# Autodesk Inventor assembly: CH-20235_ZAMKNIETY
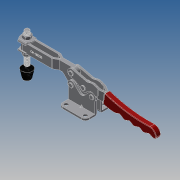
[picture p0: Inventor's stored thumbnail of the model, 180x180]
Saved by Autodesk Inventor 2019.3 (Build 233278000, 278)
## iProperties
Company: ·L?¤¤?
Created: 2010-06
Part Number: CH-20235_ZAMKNIETY
Material: Ogólny
Description: STEP AP203
Document SubType Name: Assembly
Designer: CADENGINEERING4
Sending System: SolidWorks 2005179
Preprocessor: SwSTEP 2.0
Title: CH-20235.STEP
Author: ·L?¥Î?
Revision Number: ANY
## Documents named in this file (9)
- E:\STRONA\Horizontal toggle clamp\CH-20235\CH-20235_ZAMKNIETY.iam
- E:\STRONA\Horizontal toggle clamp\CH-20235\20235-01___.ipt
- E:\STRONA\Horizontal toggle clamp\CH-20235\20235-05___.ipt
- E:\STRONA\Horizontal toggle clamp\CH-20235\20235-02___.ipt
- E:\STRONA\Horizontal toggle clamp\CH-20235\20235-04___.ipt
- E:\STRONA\Horizontal toggle clamp\CH-20235\FW380___.ipt
- E:\STRONA\Horizontal toggle clamp\CH-20235\38312-02___.ipt
- E:\STRONA\Horizontal toggle clamp\CH-20235\CH-FC-38312___.ipt
- E:\STRONA\Horizontal toggle clamp\CH-20235\20235-03___.ipt
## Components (14 placed, 14 different names)
1. 20235-01_??_1 — Zestawiające:13, Zestawiające:14, Zestawiające:15, Zestawiające:16, Zestawiające:21, Zestawiające:22, Zestawiające:23, Zestawiające:24, Przejściowe:1
2. 20235-05_??_2 — Zestawiające:15, Zestawiające:16
3. 20235-05_??_3 — Zestawiające:19, Zestawiające:20
4. 20235-02_??_4 — Zestawiające:7, Zestawiające:8, Kątowe:1, Zestawiające:9, Zestawiające:21, Zestawiające:22, Zestawiające:27
5. 20235-04_??_5 — Zestawiające:10, Zestawiające:11, Zestawiające:12, Zestawiające:13, Zestawiające:14, Zestawiające:17, Zestawiające:18
6. FW380_??_6 — Zestawiające:4, Zestawiające:6, Zestawiające:8, Równoległe:2, Kątowe:1
7. 38312-02_??_7 — Zestawiające:1, Zestawiające:3
8. 20235-05_??_8 — Zestawiające:23, Zestawiające:24
9. 20235-04_??_9 — Zestawiające:10, Zestawiające:11, Zestawiające:12
10. 38312-02_??_10 — Zestawiające:5, Zestawiające:6, Równoległe:1
11. CH-FC-38312_??_11 — Zestawiające:1, Zestawiające:2, Zestawiające:4, Zestawiające:5, Równoległe:1, Zestawiające:9
12. 20235-05_??_12 — Zestawiające:25, Zestawiające:26, Zestawiające:27
13. FW380_??_13 — Zestawiające:2, Zestawiające:3, Zestawiające:7, Równoległe:2
14. 20235-03_??_14 — Zestawiające:17, Zestawiające:18, Zestawiające:19, Zestawiające:20, Zestawiające:25, Zestawiające:26, Przejściowe:1
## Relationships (31: Mate 27, Flush 2, Angle 1, Transitional 1)
- Zestawiające:1 [Mate]: 38312-02_??_7 ↔ CH-FC-38312_??_11
- Zestawiające:2 [Mate]: CH-FC-38312_??_11 ↔ FW380_??_13
- Zestawiające:3 [Mate]: 38312-02_??_7 ↔ FW380_??_13
- Zestawiające:4 [Mate]: FW380_??_6 ↔ CH-FC-38312_??_11
- Zestawiające:5 [Mate]: 38312-02_??_10 ↔ CH-FC-38312_??_11
- Zestawiające:6 [Mate]: FW380_??_6 ↔ 38312-02_??_10
- Równoległe:1 [Flush]: 38312-02_??_10 ↔ CH-FC-38312_??_11
- Zestawiające:7 [Mate]: 20235-02_??_4 ↔ FW380_??_13
- Zestawiające:8 [Mate]: 20235-02_??_4 ↔ FW380_??_6
- Równoległe:2 [Flush]: FW380_??_6 ↔ FW380_??_13
- Kątowe:1 [Angle]: 20235-02_??_4 ↔ FW380_??_6
- Zestawiające:9 [Mate]: 20235-02_??_4 ↔ CH-FC-38312_??_11
- Zestawiające:10 [Mate]: 20235-04_??_5 ↔ 20235-04_??_9
- Zestawiające:11 [Mate]: 20235-04_??_5 ↔ 20235-04_??_9
- Zestawiające:12 [Mate]: 20235-04_??_5 ↔ 20235-04_??_9
- Zestawiające:13 [Mate]: 20235-01_??_1 ↔ 20235-04_??_5
- Zestawiające:14 [Mate]: 20235-01_??_1 ↔ 20235-04_??_5
- Zestawiające:15 [Mate]: 20235-01_??_1 ↔ 20235-05_??_2
- Zestawiające:16 [Mate]: 20235-01_??_1 ↔ 20235-05_??_2
- Zestawiające:17 [Mate]: 20235-04_??_5 ↔ 20235-03_??_14
- Zestawiające:18 [Mate]: 20235-04_??_5 ↔ 20235-03_??_14
- Zestawiające:19 [Mate]: 20235-05_??_3 ↔ 20235-03_??_14
- Zestawiające:20 [Mate]: 20235-05_??_3 ↔ 20235-03_??_14
- Zestawiające:21 [Mate]: 20235-01_??_1 ↔ 20235-02_??_4
- Zestawiające:22 [Mate]: 20235-01_??_1 ↔ 20235-02_??_4
- Zestawiające:23 [Mate]: 20235-01_??_1 ↔ 20235-05_??_8
- Zestawiające:24 [Mate]: 20235-01_??_1 ↔ 20235-05_??_8
- Zestawiające:25 [Mate]: 20235-05_??_12 ↔ 20235-03_??_14
- Zestawiające:26 [Mate]: 20235-05_??_12 ↔ 20235-03_??_14
- Zestawiające:27 [Mate]: 20235-02_??_4 ↔ 20235-05_??_12
- Przejściowe:1 [Transitional]: 20235-01_??_1 ↔ 20235-03_??_14
